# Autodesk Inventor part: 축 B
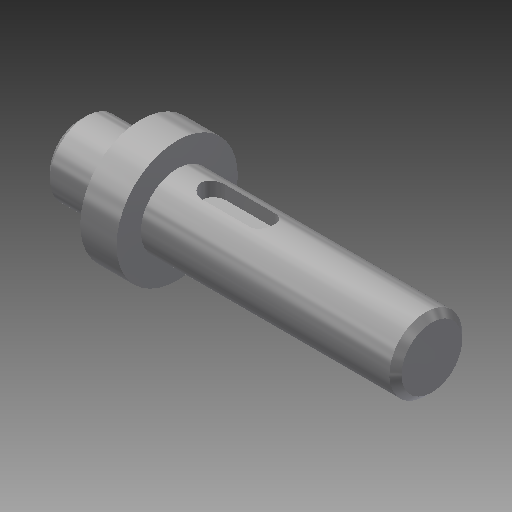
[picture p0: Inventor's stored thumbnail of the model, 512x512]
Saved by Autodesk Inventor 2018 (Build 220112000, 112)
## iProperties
Created: 2020-04
Part Number: 축 B
Material: 강철, 연강
Document SubType Name: Modeling
Designer: mduedu
Density: 7.86 g/cm^3
Mass: 57.2004 g
Surface Area: 29.0657 cm^2
Volume: 7.2774 cm^3
Appearance: 강철
Author: mduedu
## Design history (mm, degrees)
revolve "회전1" stored, may be unused: angle "d11" = 90 deg
sketch "스케치3"
  geometry: L1 (0, -6)-(0, 6) reference; L2 (0, 6)-(10, 6) reference; L3 (10, 6)-(10, 10) reference; L4 (10, 10)-(16, 10) reference; L5 (16, 10)-(16, 6) reference; L6 (16, 6)-(58, 6) reference; L7 (58, 6)-(58, -6) reference; L8 (58, -6)-(16, -6) reference; L9 (16, -6)-(16, -10) reference; L10 (16, -10)-(10, -10) reference; L11 (10, -10)-(10, -6) reference; L12 (10, -6)-(0, -6) reference; L13 (20, 6)-(32, 6); L14 (32, 6)-(32, 3.5); L15 (32, 3.5)-(20, 3.5); L16 (20, 3.5)-(20, 6); 1 further point
  constraints: 8 end point, 2 parallel, 1 horizontal, 1 perpendicular, 1 point on line
  dimensions: "d17" = 12 distance of L14.end L15.end; "d18" = 2.5 distance of L13.end L14.end; "d19" = 4 distance from line of L16 L4.end
extrude "돌출2" cut sketch "스케치3" stored distance "d20" = 4; taper "d21" = 0 deg
fillet "모깎기2" dims "d22" = 2
chamfer "모따기1" distance "d23" = 1; stored, may be unused: second distance "d24" = 2, angle "d25" = 45 deg
chamfer "모따기2" distance "d26" = 1; stored, may be unused: second distance "d27" = 2, angle "d28" = 45 deg
fillet "모깎기3" dims "d29" = 0.3
node "솔리드1"
sketch "스케치1"
  geometry: L1 (0, 0)-(10, 0); L2 (10, 0)-(10, 6); L3 (10, 6)-(0, 6); L4 (0, 6)-(0, 0); L5 (10, 0)-(16, 0); L6 (16, 0)-(16, 10); L7 (16, 10)-(10, 10); L8 (10, 10)-(10, 0); L9 (16, 0)-(58, 0); L10 (58, 0)-(58, 6); L11 (58, 6)-(16, 6); L12 (16, 6)-(16, 0); L13 (58, 0)-(58, 0); L14 (58, 5)-(58, 0)
  constraints: 28 end point, 6 parallel, 4 horizontal, 3 perpendicular
  dimensions: "d2" = 10 distance of L2.end L3.end; "d3" = 6 distance of L6.end L7.end; "d7" = 12 diameter of L11 L9; "d8" = 12 diameter of L3 L1; "d9" = 20 diameter of L7 L5; "d36" = 58 distance between parallel lines of L10 L4
node "절단 모서리 투영2"
